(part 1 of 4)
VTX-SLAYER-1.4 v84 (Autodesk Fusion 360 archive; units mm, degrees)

design "VTX-SLAYER-1.0" references "prop", "M2 screw size FLAT WASHER", "motor", "M3 x 0.5mm Thread 16mm LONG SOCKET HEAD CAP SCREW", "M2 x 0.4mm Thread 5mm LONG SOCKET HEAD CAP SCREW", "M2 x 0.4mm Thread 6mm LONG SOCKET HEAD CAP SCREW", "M2 x 0.4mm Thread HEX NUT", "runcam_phoenix_2", "M2 x 0.4mm Thread 20mm LONG SOCKET HEAD CAP SCREW", "nut", "M3 x 0.5mm Thread 8mm LONG SOCKET HEAD CAP SCREW", "vtx-slayer-caddx-antenna-mount"
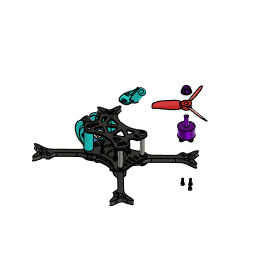
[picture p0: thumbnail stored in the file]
parameter "d278" = 4.1
parameter "d427" = 3.1
parameter "d437" = 4.2
parameter "d451" = 2.2
parameter "d614" = 15
parameter "d1109" = 4
parameter "d1134" = 12.8 (= "25.6 mm / 2.0")
canvas "Ansichtsbereich"
sketch "Skizze1" plane through (0, 0, 0) normal (0, 0, 1) x axis (1, 0, 0)
  line L1 (5.8693, -34.9991) -> (5.8693, -25.0204)
  line L2 (-57.0019, 8.0109) -> (-57.5891, 7.9385)
  line L3 (-57.259, 10.0951) -> (-57.8463, 10.0227)
  line L4 (-53.0046, 14.7338) -> (-53.0363, 15.3314)
  line L5 (-50.9075, 14.8451) -> (-50.9392, 15.4427)
  line L6 (-45.7643, 10.7703) -> (-46.3634, 10.7515)
  line L7 (-46.2975, 8.6525) -> (-45.6984, 8.6714)
  line L8 (0.8693, -39.9991) -> (-14.9589, -39.9991)
  line L9 (5.2623, -39.9991) -> (0.8693, -39.9991)
  line L10 (5.8693, -39.9991) -> (5.2623, -39.9991)
  line L11 (5.8693, -34.9991) -> (5.8693, -39.9991)
  line L12 (15.8693, -49.9991) -> (15.873, -49.9991)
  line L13 (15.8693, -29.9991) -> (15.873, -29.9991)
  line L14 (-7.6307, -25.3947) -> (-7.6307, -34.4991)
  curve K1 (-7.6307, -25.3947) -> (-10.9746, -20.0338)
  curve K2 (-12.5574, -19.204) -> (-9.3918, -20.8636)
  curve K3 (-7.6307, -25.7698) -> (-7.6307, -25.0196)
  line L15 (-20.2292, -25.643) -> (-53.829, 7.2456)
  line L16 (-49.632, 11.5333) -> (-16.0322, -21.3552)
  curve K4 (-25.1132, -12.4665) -> (-14.076, -18.1856)
  curve K5 (-42.6895, -3.6581) -> (-58.4159, 4.3179)
  curve K6 (-39.5769, 1.6911) -> (-43.0511, 12.8356)
  curve K7 (-39.0355, 1.1612) -> (-40.1182, 2.221)
  curve K8 (-42.3474, 12.2194) -> (-43.7548, 13.4517)
  curve K9 (-41.833, -4.4965) -> (-43.5461, -2.8197)
  curve K10 (-57.742, 4.1664) -> (-59.0898, 4.4693)
  curve K11 (-26.2747, -11.3295) -> (-23.9517, -13.6034)
  curve K12 (-14.6037, -17.8994) -> (-13.5483, -18.4717)
  curve K13 (-26.9801, -19.0351) -> (-22.3176, -27.7327)
  curve K14 (-22.9195, -27.2509) -> (-21.7157, -28.2145)
  curve K15 (-27.6566, -18.3729) -> (-26.3035, -19.6973)
  line L17 (-65.0703, 8.0734) -> (-57.1305, 9.053)
  line L18 (-52.3801, 22.7782) -> (-51.956, 14.7895)
  curve K16 (5.8693, -25.0204) -> (-14.076, -18.1856)
  curve K17 (-12.5184, -19.0318) -> (-15.6337, -17.3393)
  curve K18 (10.1662, -25.0241) -> (1.5724, -25.0168)
  curve K19 (-22.3176, -27.7327) -> (-10.6307, -34.4991)
  curve K20 (-10.6307, -32.2321) -> (-10.6307, -36.7662)
  curve K21 (-17.5546, -29.5) -> (-14.0454, -29.5)
  curve K22 (-23.5931, -26.7897) -> (-21.042, -28.6757)
  curve K23 (-43.0511, 12.8356) -> (-47.6742, 16.5575)
  curve K24 (-47, 15.6) -> (-48.3483, 17.515)
  curve K25 (-42.3474, 12.2194) -> (-43.7548, 13.4517)
  curve K26 (-47.6742, 16.5575) -> (-58.4159, 4.3179)
  curve K27 (-62.844, 5.395) -> (-53.9878, 3.2408)
  curve K28 (-65.2846, 9.8103) -> (-64.856, 6.3366)
  curve K29 (-54.7508, 15.3088) -> (-57.8176, 12.0705)
  curve K30 (-50.6326, 22.871) -> (-54.1277, 22.6854)
  curve K31 (-46.4995, 14.804) -> (-48.8488, 18.311)
  circle C1 centre (-51.7305, 9.3895) radius 2.7
  circle C2 centre (-57.7177, 8.9806) radius 1.05
  circle C3 centre (-57.1305, 9.053) radius 1.05
  circle C4 centre (-51.9878, 15.3871) radius 1.05
  circle C5 centre (-51.956, 14.7895) radius 1.05
  circle C6 centre (-46.3305, 9.702) radius 1.05
  circle C7 centre (-45.7313, 9.7208) radius 1.05
  circle C8 centre (-18.1307, -23.4991) radius 1.55
  circle C9 centre (-4.1307, -29.9991) radius 1.05
  circle C10 centre (15.873, -29.9991) radius 1.05
  circle C11 centre (29.8693, -23.4991) radius 1.55
  circle C12 centre (5.8693, -39.9991) radius 5
  circle C13 centre (-18.1307, -56.4991) radius 1.55
  circle C14 centre (15.873, -49.9991) radius 1.05
  circle C15 centre (29.8693, -56.4991) radius 1.55
  circle C16 centre (-4.1307, -49.9991) radius 1.05
  circle C17 centre (-9.1307, -34.4991) radius 1.5
  circle C18 centre (-18.1307, -23.4991) radius 3
  circle C19 centre (-51.7305, 9.3895) radius 3
  point P12 (-57.0019, 8.0109)
  point P11 (-57.5891, 7.9385)
  point P14 (-57.259, 10.0951)
  point P13 (-57.8463, 10.0227)
  point P15 (-53.0363, 15.3314)
  point P18 (-50.9075, 14.8451)
  point P19 (-46.3634, 10.7515)
  point P20 (-45.7643, 10.7703)
  point P21 (-45.6984, 8.6714)
  point P22 (-46.2975, 8.6525)
  point P17 (-50.9392, 15.4427)
  point P16 (-53.0046, 14.7338)
  point P29 (0.8693, -39.9991)
  point P30 (5.8693, -34.9991)
  point P24 (-18.1307, -23.4991)
  point P27 (29.8693, -23.4991)
  point P28 (5.8693, -39.9991)
  point P32 (5.8693, -39.9991)
  point P34 (15.873, -49.9991)
  point P36 (15.873, -49.9991)
  point P26 (15.873, -29.9991)
  point P38 (15.873, -29.9991)
  point P41 (-10.6307, -34.4991)
  point P43 (-9.1307, -34.4991)
  point P44 (-7.6307, -34.4991)
  point P46 (-10.9746, -20.0338)
  point P45 (-7.6307, -25.3947)
  point P49 (-7.6307, -25.7698)
  point P52 (-53.829, 7.2456)
  point P53 (-20.2292, -25.643)
  point P54 (-16.0322, -21.3552)
  point P55 (-49.632, 11.5333)
  point P23 (-14.076, -18.1856)
  point P56 (-14.076, -18.1856)
  point P57 (-25.1132, -12.4665)
  point P58 (-42.6895, -3.6581)
  point P59 (-39.5769, 1.6911)
  point P61 (-39.0355, 1.1612)
  point P86 (-43.0511, 12.8356)
  point P65 (-41.833, -4.4965)
  point P85 (-58.4159, 4.3179)
  point P69 (-26.2747, -11.3295)
  point P73 (-26.9801, -19.0351)
  point P72 (-22.3176, -27.7327)
  point P77 (-27.6566, -18.3729)
  point P6 (-57.1305, 9.053)
  point P81 (-57.1305, 9.053)
  point P8 (-51.956, 14.7895)
  point P83 (-51.956, 14.7895)
  point P7 (-51.9878, 15.3871)
  point P5 (-57.7177, 8.9806)
  point P78 (-65.0703, 8.0734)
  point P82 (-65.0703, 8.0734)
  point P80 (-52.3801, 22.7782)
  point P84 (-52.3801, 22.7782)
  point P4 (5.8693, -25.0204)
  point P42 (-15.8, -29.5)
  point P97 (-47.6742, 16.5575)
  point P79 (-56.2842, 13.6897)
  point P112 (-10.9746, -20.0338)
  point P70 (-13.5483, -18.4717)
  point P62 (-43.7548, 13.4517)
  point P100 (-43.7548, 13.4517)
  point P25 (-4.1307, -29.9991)
  point P39 (15.8693, -29.9991)
  point P2 (-51.7305, 9.3895)
  point P9 (-46.3305, 9.702)
  point P37 (15.8693, -49.9991)
  point P40 (-4.1307, -49.9991)
  point P3 (-14.9589, -39.9991)
  point P104 (-64.856, 6.3366)
  point P105 (-65.2846, 9.8103)
  point P108 (-54.1277, 22.6854)
  point P109 (-50.6326, 22.871)
  horizontal L8
  perpendicular L1 L8
  coincident C3 P12
  tangent C3 L2
  coincident C2 P11
  tangent C2 L2
  coincident C3 P14
  tangent C3 L3
  coincident C2 P13
  tangent C2 L3
  coincident C4 P15
  tangent C4 L4
  tangent C5 L4
  coincident C5 P18
  tangent C5 L5
  tangent C4 L5
  coincident C6 P19
  tangent C6 L6
  coincident C7 P20
  tangent C7 L6
  coincident C7 P21
  tangent C7 L7
  coincident C6 P22
  tangent C6 L7
  coincident C4 P17
  coincident C5 P16
  coincident C12 P29
  coincident C12 P30
  perpendicular L1 L9
  horizontal P24 P27
  parallel L9 L10
  perpendicular L9 L11
  coincident P28 P32
  symmetric C8 L8 C13
  symmetric C10 L8 C14
  symmetric C11 L8 C15
  coincident P34 P36
  coincident P26 P38
  parallel L12 L13
  symmetric C9 L8 C16
  coincident P41 C17
  horizontal P41 P43
  coincident C17 P44
  tangent C17 L14
  vertical L14
  midpoint P46 K2
  midpoint P45 K3
  coincident L14 P49
  concentric C8 C18
  concentric C1 C19
  coincident C19 P52
  coincident C18 P53
  tangent C18 L15
  coincident C18 P54
  coincident C19 P55
  tangent C19 L16
  tangent C19 L15
  tangent C18 L16
  coincident P23 P56
  coincident L16 P57
  coincident L15 P58
  coincident L16 P59
  midpoint P59 K7
  coincident L16 P61
  parallel L16 K7
  midpoint K8 P86
  midpoint P58 K9
  coincident L15 P65
  parallel L15 K9
  midpoint K10 P85
  midpoint P57 K11
  coincident L16 P69
  midpoint P56 K12
  coincident L15 P73
  midpoint P72 K14
  midpoint P73 K15
  coincident L15 P77
  parallel L15 K15
  coincident P6 P81
  coincident P8 P83
  coincident P7 L18
  coincident P5 L17
  coincident P78 P82
  coincident P80 P84
  midpoint P23 K17
  midpoint P4 K18
  midpoint P41 K20
  midpoint P42 K21
  midpoint P72 K22
  midpoint P97 K24
  midpoint P86 K25
  midpoint P85 K27
  midpoint P78 K28
  midpoint P79 K29
  midpoint P80 K30
  midpoint P97 K31
  coincident P46 P112
  coincident P70 K16
  perpendicular L17 K28
  perpendicular L18 K30
  coincident P62 P100
  dimension "d4" diameter C1 = 5.4
  dimension "d8" diameter C2 = 2.1
  dimension "d9" diameter C3 = 2.1
  dimension "d10" diameter C4 = 2.1
  dimension "d11" diameter C5 = 2.1
  dimension "d12" diameter C6 = 2.1
  dimension "d13" diameter C7 = 2.1
  dimension "d14" diameter C8 = 3.1
  dimension "d16" diameter C9 = 2.1
  dimension "d17" diameter C10 = 2.1 (= "d16")
  dimension "d20" diameter C11 = 3.1 (= "d14")
  dimension "d23" distance P25 P39 = 20
  dimension "d27" diameter C12 = 10
  dimension "d50" distance P4 P28 = 14.9787
  dimension "d58" distance P24 P27 = 48 (= "d103 * 2")
  dimension "d102" distance L1 P25 = 10
  dimension "d103" distance L1 P24 = 24
  dimension "d145" distance P2 P6 = 5.4
  dimension "d146" distance P2 P9 = 5.4
  dimension "d148" distance P2 P8 = 5.4
  dimension "d265" distance P2 L1 = 57.5997
  dimension "d266" distance P2 L8 = 49.3886
  dimension "d267" distance P24 L8 = 16.5
  dimension "d272" distance P25 L8 = 10
  dimension "d273" distance P37 P39 = 20
  dimension "d274" distance P37 P40 = 20
  dimension "d520" diameter C17 = 3
  dimension "d521" distance P28 P43 = 15
  dimension "d522" distance L8 P43 = 5.5
  dimension "d523" distance P3 P29 = 15.8282
  dimension "d669" diameter C18 = 6
  dimension "d670" diameter C19 = 6
  dimension "d709" distance P83 P84 = 8
  dimension "d710" distance P81 P82 = 8
  dimension "d1085" distance P104 P105 = 3.5
  dimension "d1086" distance P108 P109 = 3.5
extrude "Extrusion4" new body sketch "Skizze1" profile of C1 K23 C2 C3 C4 C5 C6 C7 L2 L3 L4 L5 L6 L7 C8 K19 C17 L14 K1 L15 L16 K4 K5 K6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 along normal blind 5 bodies "arm-fr"
work_plane "Arbeitsebene3" RotateAngle -90
work_plane "Arbeitsebene4" RotateAngle 90
mirror "Spiegeln6" mirrorStitchTolerance 0.1 bodies "arm-rr"
mirror "Spiegeln7" mirrorStitchTolerance 0.1 bodies "arm-fl", "arm-rl"
sketch "Skizze43" plane through (0, 0, 5) normal (0, 0, 1) x axis (-1, 0, 0)
  line L1 (53.0363, -15.3314) -> (53.0046, -14.7338)
  line L2 (50.9075, -14.8451) -> (50.9392, -15.4427)
  line L3 (45.7643, -10.7703) -> (46.3634, -10.7515)
  line L4 (46.2975, -8.6525) -> (45.6984, -8.6714)
  line L5 (57.5891, -7.9385) -> (57.0019, -8.0109)
  line L6 (57.259, -10.0951) -> (57.8463, -10.0227)
  curve K1 (10.6307, 34.4991) -> (22.3176, 27.7327)
  line L7 (53.0046, 94.732) -> (53.0363, 95.3296)
  line L8 (50.9392, 95.441) -> (50.9075, 94.8433)
  line L9 (45.6984, 88.6696) -> (46.2975, 88.6508)
  line L10 (46.3634, 90.7497) -> (45.7643, 90.7686)
  line L11 (57.0019, 88.0092) -> (57.5891, 87.9367)
  line L12 (57.8463, 90.0209) -> (57.259, 90.0934)
  curve K2 (10.6307, 45.4991) -> (22.3176, 52.2655)
  line L13 (-64.7748, 95.3296) -> (-64.7431, 94.732)
  line L14 (-62.646, 94.8433) -> (-62.6778, 95.441)
  line L15 (-57.5028, 90.7686) -> (-58.1019, 90.7497)
  line L16 (-58.0361, 88.6508) -> (-57.4369, 88.6696)
  line L17 (-69.3276, 87.9367) -> (-68.7404, 88.0092)
  line L18 (-68.9976, 90.0934) -> (-69.5848, 90.0209)
  curve K3 (-22.3693, 45.4991) -> (-34.0561, 52.2655)
  line L19 (-64.7431, -14.7338) -> (-64.7748, -15.3314)
  line L20 (-62.6778, -15.4427) -> (-62.646, -14.8451)
  line L21 (-57.4369, -8.6714) -> (-58.0361, -8.6525)
  line L22 (-58.1019, -10.7515) -> (-57.5028, -10.7703)
  line L23 (-68.7404, -8.0109) -> (-69.3276, -7.9385)
  line L24 (-69.5848, -10.0227) -> (-68.9976, -10.0951)
  curve K4 (-22.3693, 34.4991) -> (-34.0561, 27.7327)
  line L25 (-2.454, 39.9991) -> (16.5436, 39.9991)
  line L26 (-5.8693, 35.997) -> (-5.8693, 24.0226)
  line L27 (-45, 39.9991) -> (35, 39.9991)
  line L28 (-5.8693, 61) -> (-5.8693, 13.9501)
  curve K5 (14.9589, 39.9991) -> (13.0937, 29.8846)
  curve K6 (5.0594, 23.381) -> (7.6307, 25.3947)
  curve K7 (7.6307, 23.731) -> (7.6307, 27.0584)
  curve K8 (3.3466, 23.9517) -> (6.7722, 22.8102)
  curve K9 (14.9589, 42.2662) -> (14.9589, 37.732)
  curve K10 (14.715, 29.209) -> (11.4725, 30.5602)
  curve K11 (15.7694, 31.8891) -> (15.1694, 30.2891)
  line L29 (-5.8693, 33.7991) -> (3.3307, 33.7991)
  line L30 (7.6307, 25.3947) -> (7.6307, 34.4991)
  curve K12 (9.6778, 20.9358) -> (7.6307, 25.3947)
  line L31 (-19.3693, 54.6035) -> (-19.3693, 45.4991)
  curve K13 (-21.4163, 59.0625) -> (-19.3693, 54.6035)
  line L32 (-19.3693, 34.4991) -> (-19.3693, 25.3947)
  line L33 (7.6307, 45.4991) -> (7.6307, 54.6035)
  curve K14 (10.9746, 20.0338) -> (9.6778, 20.9358)
  curve K15 (-22.7131, 59.9644) -> (-21.4163, 59.0625)
  curve K16 (9.6778, 59.0625) -> (7.6307, 54.6035)
  curve K17 (-21.4163, 20.9358) -> (-19.3693, 25.3947)
  curve K18 (10.9746, 59.9644) -> (9.6778, 59.0625)
  curve K19 (-22.7131, 20.0338) -> (-21.4163, 20.9358)
  curve K20 (43.0511, -12.8356) -> (39.5769, -1.6911)
  curve K21 (25.1132, 12.4665) -> (14.076, 18.1856)
  line L34 (39.5769, -1.6911) -> (25.1132, 12.4665)
  curve K22 (43.0511, 92.8338) -> (39.5769, 81.6893)
  line L35 (25.1132, 67.5318) -> (39.5769, 81.6893)
  curve K23 (25.1132, 67.5318) -> (14.076, 61.8127)
  curve K24 (47.6742, 96.5557) -> (43.0511, 92.8338)
  curve K25 (-54.7896, 92.8338) -> (-51.3154, 81.6893)
  curve K26 (-36.8517, 67.5318) -> (-25.8145, 61.8127)
  line L36 (-51.3154, 81.6893) -> (-36.8517, 67.5318)
  curve K27 (-54.7896, -12.8356) -> (-51.3154, -1.6911)
  line L37 (-36.8517, 12.4665) -> (-51.3154, -1.6911)
  curve K28 (-36.8517, 12.4665) -> (-25.8145, 18.1856)
  curve K29 (-59.4127, -16.5575) -> (-54.7896, -12.8356)
  curve K30 (42.6895, 3.6581) -> (58.4159, -4.3179)
  line L38 (26.9801, 19.0351) -> (42.6895, 3.6581)
  curve K31 (22.3176, 27.7327) -> (26.9801, 19.0351)
  curve K32 (22.3176, 52.2655) -> (26.9801, 60.9632)
  line L39 (42.6895, 76.3401) -> (26.9801, 60.9632)
  curve K33 (42.6895, 76.3401) -> (58.4159, 84.3161)
  curve K34 (-59.4127, 96.5557) -> (-54.7896, 92.8338)
  curve K35 (-54.4281, 76.3401) -> (-70.1544, 84.3161)
  line L40 (-38.7186, 60.9632) -> (-54.4281, 76.3401)
  curve K36 (-34.0561, 52.2655) -> (-38.7186, 60.9632)
  curve K37 (-34.0561, 27.7327) -> (-38.7186, 19.0351)
  line L41 (-54.4281, 3.6581) -> (-38.7186, 19.0351)
  curve K38 (-54.4281, 3.6581) -> (-70.1544, -4.3179)
  curve K39 (52.3801, -22.7782) -> (47.6742, -16.5575)
  curve K40 (65.0703, -8.0734) -> (52.3801, -22.7782)
  curve K41 (52.3801, 102.7764) -> (47.6742, 96.5557)
  curve K42 (-64.1186, 102.7764) -> (-59.4127, 96.5557)
  curve K43 (-76.8088, 88.0717) -> (-64.1186, 102.7764)
  curve K44 (-64.1186, -22.7782) -> (-59.4127, -16.5575)
  curve K45 (65.0703, 88.0717) -> (52.3801, 102.7764)
  curve K46 (-76.8088, -8.0734) -> (-64.1186, -22.7782)
  curve K47 (-5.8693, 25.0204) -> (14.076, 18.1856)
  curve K48 (58.4159, -4.3179) -> (65.0703, -8.0734)
  curve K49 (58.4159, 84.3161) -> (65.0703, 88.0717)
  curve K50 (-70.1544, 84.3161) -> (-76.8088, 88.0717)
  curve K51 (-70.1544, -4.3179) -> (-76.8088, -8.0734)
  curve K52 (14.076, 18.1856) -> (10.9746, 20.0338)
  curve K53 (47.6742, -16.5575) -> (43.0511, -12.8356)
  curve K54 (14.076, 61.8127) -> (10.9746, 59.9644)
  curve K55 (-25.8145, 18.1856) -> (-22.7131, 20.0338)
  curve K56 (-25.8145, 61.8127) -> (-22.7131, 59.9644)
  arc A1 centre (51.9878, -15.3871) radius 1.05 clockwise from (53.0363, -15.3314) to (50.9392, -15.4427)
  arc A2 centre (51.956, -14.7895) radius 1.05 clockwise from (50.9075, -14.8451) to (53.0046, -14.7338)
  circle C1 centre (18.1307, 23.4991) radius 1.55
  arc A3 centre (46.3305, -9.702) radius 1.05 clockwise from (46.2975, -8.6525) to (46.3634, -10.7515)
  arc A4 centre (45.7313, -9.7208) radius 1.05 clockwise from (45.7643, -10.7703) to (45.6984, -8.6714)
  arc A5 centre (57.7177, -8.9806) radius 1.05 clockwise from (57.5891, -7.9385) to (57.8463, -10.0227)
  arc A6 centre (57.1305, -9.053) radius 1.05 clockwise from (57.259, -10.0951) to (57.0019, -8.0109)
  circle C2 centre (51.7305, -9.3895) radius 2.7
  arc A7 centre (9.1307, 34.4991) radius 1.5 clockwise from (7.6307, 34.4991) to (10.6307, 34.4991)
  arc A8 centre (51.956, 94.7877) radius 1.05 clockwise from (53.0046, 94.732) to (50.9075, 94.8433)
  arc A9 centre (51.9878, 95.3853) radius 1.05 clockwise from (50.9392, 95.441) to (53.0363, 95.3296)
  circle C3 centre (18.1307, 56.4991) radius 1.55
  arc A10 centre (46.3305, 89.7003) radius 1.05 clockwise from (46.3634, 90.7497) to (46.2975, 88.6508)
  arc A11 centre (45.7313, 89.7191) radius 1.05 clockwise from (45.6984, 88.6696) to (45.7643, 90.7686)
  arc A12 centre (57.1305, 89.0513) radius 1.05 clockwise from (57.0019, 88.0092) to (57.259, 90.0934)
  arc A13 centre (57.7177, 88.9788) radius 1.05 clockwise from (57.8463, 90.0209) to (57.5891, 87.9367)
  circle C4 centre (51.7305, 89.3877) radius 2.7
  arc A14 centre (9.1307, 45.4991) radius 1.5 clockwise from (10.6307, 45.4991) to (7.6307, 45.4991)
  arc A15 centre (-63.7263, 95.3853) radius 1.05 clockwise from (-64.7748, 95.3296) to (-62.6778, 95.441)
  arc A16 centre (-63.6946, 94.7877) radius 1.05 clockwise from (-62.646, 94.8433) to (-64.7431, 94.732)
  circle C5 centre (-29.8693, 56.4991) radius 1.55
  arc A17 centre (-58.069, 89.7003) radius 1.05 clockwise from (-58.0361, 88.6508) to (-58.1019, 90.7497)
  arc A18 centre (-57.4698, 89.7191) radius 1.05 clockwise from (-57.5028, 90.7686) to (-57.4369, 88.6696)
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  point P107 (13.0937, 29.8846)
  point P111 (-5.8693, 39.9991)
  point P109 (7.6307, 25.3947)
  point P110 (5.0594, 23.381)
  point P108 (15.4694, 31.0891)
  point P128 (-5.8693, 33.7991)
  point P114 (7.6307, 27.0584)
  parallel L25 L27
  perpendicular L27 L28
  coincident K1 P107
  coincident L28 P111
  coincident L27 P111
  midpoint P109 K7
  midpoint P110 K8
  midpoint P107 K10
  midpoint P108 K11
  horizontal L29
  coincident L26 P128
  coincident L28 P128
  parallel L28 K9
  coincident P109 L30
  coincident P114 L30
  dimension "d356" diameter = 4.2
  dimension "d363" diameter = 3.1
  dimension "d503" distance P111 P128 = 6.2
extrude "Extrusion55" new body sketch "Skizze43" against normal blind 2 bodies "m-center"
mirror "Spiegeln20" mirrorStitchTolerance 0.1
mirror "Spiegeln21" mirrorStitchTolerance 0.1
sketch "Skizze4" plane through (0, 0, 0) normal (0, 0, -1) x axis (1, 0, 0)
  line L1 (-45.6984, -8.6714) -> (-46.2975, -8.6525)
  line L2 (-46.3634, -10.7515) -> (-45.7643, -10.7703)
  line L3 (-53.0046, -14.7338) -> (-53.0363, -15.3314)
  line L4 (-50.9392, -15.4427) -> (-50.9075, -14.8451)
  line L5 (-57.0019, -8.0109) -> (-57.5891, -7.9385)
  line L6 (-57.8463, -10.0227) -> (-57.259, -10.0951)
  line L7 (5.8693, 34.9991) -> (5.8693, 39.9991)
  line L8 (5.8693, 34.9991) -> (5.8693, 25.0204)
  curve K1 (-22.3176, 27.7327) -> (-10.6307, 34.4991)
  curve K2 (-13.2943, 29.8104) -> (-14.9589, 39.9991)
  curve K3 (-13.0937, 29.8846) -> (-13.2943, 29.8104)
  curve K4 (-5.4893, 23.275) -> (-7.6307, 25.3947)
  line L9 (-34.1307, 39.9991) -> (5.8693, 39.9991)
  line L10 (-34.1307, 46.2008) -> (-34.1307, 39.9991)
  line L11 (-12.5862, 69.6661) -> (-34.1307, 46.2008)
  line L12 (-57.5891, 87.9367) -> (-57.0019, 88.0092)
  line L13 (-57.259, 90.0934) -> (-57.8463, 90.0209)
  line L14 (-53.0363, 95.3296) -> (-53.0046, 94.732)
  line L15 (-50.9075, 94.8433) -> (-50.9392, 95.441)
  line L16 (-45.7643, 90.7686) -> (-46.3634, 90.7497)
  line L17 (-46.2975, 88.6508) -> (-45.6984, 88.6696)
  curve K5 (-22.3176, 52.2655) -> (-10.6307, 45.4991)
  curve K6 (-1.6863, 55.6114) -> (-9.6778, 59.0625)
  curve K7 (0.3253, 55.2725) -> (-3.698, 55.9502)
  curve K8 (-3.0083, 56.2858) -> (-3.1917, 58.5142)
  curve K9 (-8.5538, 58.2617) -> (-10.8018, 59.8633)
  curve K10 (-2.18, 58.2549) -> (-5.9502, 58.4922)
  line L18 (5.8693, 35.997) -> (5.8693, 24.0226)
  line L19 (68.7404, 88.0092) -> (69.3276, 87.9367)
  line L20 (69.5848, 90.0209) -> (68.9976, 90.0934)
  line L21 (64.7431, 94.732) -> (64.7748, 95.3296)
  line L22 (62.6778, 95.441) -> (62.646, 94.8433)
  line L23 (57.4369, 88.6696) -> (58.0361, 88.6508)
  line L24 (58.1019, 90.7497) -> (57.5028, 90.7686)
  curve K11 (34.0561, 52.2655) -> (22.3693, 45.4991)
  curve K12 (26.6564, 39.9983) -> (33.3763, 51.7943)
  curve K13 (26.6564, 38.371) -> (26.6564, 41.6256)
  curve K14 (32.9215, 51.5105) -> (33.8311, 52.0782)
  line L25 (40, 39.9991) -> (5.8693, 39.9991)
  line L26 (-29.6307, 42.9991) -> (-13.1687, 42.9991)
  line L27 (-13.1687, 48.9991) -> (-25.1307, 48.9991)
  line L28 (-13.1687, 42.9991) -> (-13.1687, 48.9991)
  line L29 (-20.1687, 42.9991) -> (-29.6307, 42.9991)
  line L30 (-14.6007, 50.4991) -> (-25.1307, 50.4991)
  line L31 (-12.0137, 44.4991) -> (-29.6307, 44.4991)
  line L32 (-12.0137, 41.4991) -> (-29.6307, 41.4991)
  line L33 (-14.6007, 47.4991) -> (-25.1307, 47.4991)
  curve K15 (-7.6307, 25.3947) -> (-9.6778, 20.9358)
  line L34 (-7.6307, 34.4991) -> (-7.6307, 25.3947)
  line L35 (-7.6307, 25.3947) -> (-7.6307, 34.4991)
  line L36 (-7.6307, 54.6035) -> (-7.6307, 45.4991)
  curve K16 (19.3693, 54.6035) -> (21.4163, 59.0625)
  line L37 (19.3693, 45.4991) -> (19.3693, 54.6035)
  line L38 (24.3247, 69.6661) -> (45.8693, 46.2008)
  curve K17 (-7.6307, 54.6035) -> (-9.6778, 59.0625)
  curve K18 (13.4249, 55.6114) -> (21.4163, 59.0625)
  curve K19 (20.2923, 58.2617) -> (22.5404, 59.8633)
  curve K20 (13.9185, 58.2549) -> (17.6888, 58.4922)
  curve K21 (14.7469, 56.2858) -> (14.9302, 58.5142)
  curve K22 (11.4132, 55.2725) -> (15.4365, 55.9502)
  line L39 (22.3617, 39.9991) -> (22.3693, 45.4966)
  curve K23 (-9.6778, 20.9358) -> (-10.9746, 20.0338)
  curve K24 (21.4163, 59.0625) -> (22.7131, 59.9644)
  curve K25 (-39.5769, -1.6911) -> (-43.0511, -12.8356)
  line L40 (-25.1132, 12.4665) -> (-39.5769, -1.6911)
  curve K26 (-25.1132, 12.4665) -> (-14.076, 18.1856)
  curve K27 (-39.5769, 81.6893) -> (-43.0511, 92.8338)
  curve K28 (-9.6778, 59.0625) -> (-10.9746, 59.9644)
  curve K29 (-25.1132, 67.5318) -> (-14.076, 61.8127)
  line L41 (-39.5769, 81.6893) -> (-25.1132, 67.5318)
  curve K30 (51.3154, 81.6893) -> (54.7896, 92.8338)
  line L42 (36.8517, 67.5318) -> (51.3154, 81.6893)
  curve K31 (36.8517, 67.5318) -> (25.8145, 61.8127)
  curve K32 (-26.9801, 19.0351) -> (-22.3176, 27.7327)
  line L43 (-42.6895, 3.6581) -> (-26.9801, 19.0351)
  curve K33 (-42.6895, 3.6581) -> (-58.4159, -4.3179)
  curve K34 (-42.6895, 76.3401) -> (-58.4159, 84.3161)
  line L44 (-26.9801, 60.9632) -> (-42.6895, 76.3401)
  curve K35 (-26.9801, 60.9632) -> (-22.3176, 52.2655)
  curve K36 (38.7186, 60.9632) -> (34.0561, 52.2655)
  line L45 (54.4281, 76.3401) -> (38.7186, 60.9632)
  curve K37 (54.4281, 76.3401) -> (70.1544, 84.3161)
  line L46 (10.0693, 50.9491) -> (1.6693, 50.9491)
  line L47 (10.0693, 47.4491) -> (1.6693, 47.4491)
  curve K38 (-10.6307, 34.4991) -> (-13.0937, 29.8846)
  curve K39 (17.2278, 23.275) -> (19.3693, 25.3947)
  line L48 (19.3693, 34.4991) -> (19.3693, 25.3947)
  curve K40 (22.3693, 34.4991) -> (24.8323, 29.8846)
  curve K41 (24.8323, 29.8846) -> (25.0329, 29.8104)
  curve K42 (25.0329, 29.8104) -> (26.6974, 39.9991)
  curve K43 (25.0329, 50.1878) -> (26.6974, 39.9991)
  curve K44 (24.8323, 50.1137) -> (25.0329, 50.1878)
  curve K45 (22.3693, 45.4991) -> (24.8323, 50.1137)
  line L49 (19.3693, 54.6035) -> (19.3693, 45.4991)
  curve K46 (17.2278, 56.7233) -> (19.3693, 54.6035)
  curve K47 (-5.4893, 56.7233) -> (-7.6307, 54.6035)
  line L50 (-7.6307, 45.4991) -> (-7.6307, 54.6035)
  curve K48 (-10.6307, 45.4991) -> (-13.0937, 50.1137)
  curve K49 (-13.0937, 50.1137) -> (-13.2943, 50.1878)
  curve K50 (-13.2943, 50.1878) -> (-14.9589, 39.9991)
  curve K51 (-52.3801, -22.7782) -> (-65.0703, -8.0734)
  curve K52 (-47.6742, -16.5575) -> (-52.3801, -22.7782)
  curve K53 (-47.6742, 96.5557) -> (-52.3801, 102.7764)
  curve K54 (64.1186, 102.7764) -> (76.8088, 88.0717)
  curve K55 (59.4127, 96.5557) -> (64.1186, 102.7764)
  curve K56 (-43.0511, 92.8338) -> (-47.6742, 96.5557)
  curve K57 (-52.3801, 102.7764) -> (-65.0703, 88.0717)
  curve K58 (54.7896, 92.8338) -> (59.4127, 96.5557)
  curve K59 (5.8693, 54.9778) -> (17.2278, 56.7233)
  curve K60 (5.8693, 54.9778) -> (-5.4893, 56.7233)
  curve K61 (5.8693, 25.0204) -> (-5.4893, 23.275)
  curve K62 (5.8693, 25.0204) -> (17.2278, 23.275)
  curve K63 (-65.0703, -8.0734) -> (-58.4159, -4.3179)
  curve K64 (-65.0703, 88.0717) -> (-58.4159, 84.3161)
  curve K65 (76.8088, 88.0717) -> (70.1544, 84.3161)
  curve K66 (-10.9746, 20.0338) -> (-14.076, 18.1856)
  curve K67 (-10.9746, 59.9644) -> (-14.076, 61.8127)
  curve K68 (22.7131, 59.9644) -> (25.8145, 61.8127)
  arc A1 centre (-46.3305, -9.702) radius 1.05 clockwise from (-46.3634, -10.7515) to (-46.2975, -8.6525)
  arc A2 centre (-45.7313, -9.7208) radius 1.05 clockwise from (-45.6984, -8.6714) to (-45.7643, -10.7703)
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  point P73 (-1.6863, 55.6114)
  point P72 (-3.1, 57.4)
  point P70 (-9.6778, 59.0625)
  point P71 (-4.0651, 58.3735)
  point P110 (33.3763, 51.7943)
  point P22 (5.8693, 39.9991)
  point P115 (5.8693, 39.9991)
  point P118 (-29.6307, 42.9991)
  point P124 (-29.6307, 42.9991)
  point P125 (-12.0137, 42.9991)
  point P119 (-25.1307, 48.9991)
  point P126 (-25.1307, 48.9991)
  point P127 (-14.6007, 48.9991)
  point P136 (5.8693, 39.9991)
  point P41 (5.8693, 39.9991)
  point P44 (-34.1307, 46.2008)
  point P146 (45.8693, 46.2008)
  point P45 (-12.5862, 69.6661)
  point P147 (24.3247, 69.6661)
  point P152 (21.4163, 59.0625)
  point P153 (15.8036, 58.3735)
  point P154 (14.8385, 57.4)
  point P155 (13.4249, 55.6114)
  point P74 (-3.698, 55.9502)
  point P162 (15.4365, 55.9502)
  point P75 (0.3253, 55.2725)
  point P163 (11.4132, 55.2725)
  point P76 (-3.1917, 58.5142)
  point P160 (14.9302, 58.5142)
  point P77 (-3.0083, 56.2858)
  point P161 (14.7469, 56.2858)
  point P78 (-10.8018, 59.8633)
  point P156 (22.5404, 59.8633)
  point P79 (-8.5538, 58.2617)
  point P157 (20.2923, 58.2617)
  point P80 (-5.9502, 58.4922)
  point P158 (17.6888, 58.4922)
  point P81 (-2.18, 58.2549)
  point P159 (13.9185, 58.2549)
  point P165 (22.3617, 39.9991)
  point P117 (-13.1687, 42.9991)
  point P120 (-13.1687, 48.9991)
  point P43 (-34.1307, 39.9991)
  point P189 (1.6693, 49.1991)
  point P190 (10.0693, 49.1991)
  perpendicular L9 L10
  midpoint P73 K7
  midpoint P72 K8
  midpoint P70 K9
  midpoint P71 K10
  parallel L7 L10
  midpoint P110 K14
  coincident P22 P115
  perpendicular L7 L25
  horizontal L26
  horizontal L27
  vertical L28
  horizontal L29
  coincident P118 P124
  coincident L26 P125
  coincident P119 P126
  coincident L27 P127
  parallel L31 L32
  coincident P22 P136
  coincident P41 P136
  symmetric P44 L18 P146
  symmetric P45 L18 P147
  coincident P70 K17
  symmetric P70 L18 P152
  symmetric P71 L18 P153
  symmetric P72 L18 P154
  symmetric P73 L18 P155
  symmetric P74 L18 P162
  symmetric P75 L18 P163
  symmetric P76 L18 P160
  symmetric P77 L18 P161
  symmetric P78 L18 P156
  symmetric P79 L18 P157
  symmetric P80 L18 P158
  symmetric P81 L18 P159
  parallel L18 K13
  coincident L25 P165
  coincident K11 P110
  horizontal L46
  parallel L46 L47
  dimension "d397" distance P117 P120 = 6
  dimension "d399" distance L9 L26 = 3
  dimension "d472" diameter = 3
  dimension "d481" diameter = 3
  dimension "d482" diameter = 3
  dimension "d483" diameter = 3
  dimension "d510" diameter = 6
  dimension "d532" distance P41 P43 = 40
  dimension "d544" distance L10 P126 = 9
  dimension "d545" distance L10 P124 = 4.5
  dimension "d682" diameter = 3.5
  dimension "d683" diameter = 3.5
  dimension "d684" distance P115 P189 = 4.2
  dimension "d685" distance P115 P190 = 4.2
  dimension "d686" distance L9 P189 = 9.2
  dimension "d687" distance L25 P190 = 9.2
  dimension "d688" diameter = 4.2
extrude "Extrusion56" new body sketch "Skizze4" along normal blind 2 bodies "m-bottom"
fillet "Fillet26" radius 6
mirror "Spiegeln22" mirrorStitchTolerance 0.1
work_axis "Arbeitsachse" sketch "Skizze43"
fillet "Fillet32" radius 5
fillet "Fillet44" radius 5
copy_paste_bodies "CopyPasteBodies9"
move "Move19"
move "Move20" RotateAngle 180
sketch "topplate" plane through (0, 0, 7) normal (0, 0, 1) x axis (-1, 0, 0)
  curve K1 (9.811, 20.8371) -> (10.9746, 20.0338)
  line L1 (-26.3392, 50.4991) -> (-34.3693, 50.4991)
  line L2 (-34.3693, 47.4991) -> (-26.3392, 47.4991)
  line L3 (-23.7522, 44.4991) -> (-34.3693, 44.4991)
  line L4 (-34.3693, 41.4991) -> (-23.7522, 41.4991)
  line L5 (-2.8693, 49.9991) -> (-8.8693, 49.9991)
  line L6 (-8.8693, 45.9991) -> (-2.8693, 45.9991)
  line L7 (-2.8693, 33.9991) -> (-8.8693, 33.9991)
  line L8 (-8.8693, 29.9991) -> (-2.8693, 29.9991)
  line L9 (-23.7522, 38.4991) -> (-34.3693, 38.4991)
  line L10 (-34.3693, 35.4991) -> (-23.7522, 35.4991)
  line L11 (-26.3392, 32.4991) -> (-34.3693, 32.4991)
  line L12 (-34.3693, 29.4991) -> (-26.3392, 29.4991)
  curve K2 (14.9178, 39.9991) -> (14.9887, 41.536)
  curve K3 (14.9178, 39.9991) -> (14.9887, 38.4622)
  curve K4 (14.991, 38.4401) -> (21.2218, 28.4813)
  curve K5 (14.991, 41.5582) -> (21.2218, 51.5169)
  line L13 (21.0607, 60.4361) -> (21.7601, 59.6743)
  line L14 (-44.2889, 47.922) -> (-32.7992, 60.4361)
  line L15 (-45.8693, 36.1341) -> (-45.8693, 43.8641)
  line L16 (-32.7992, 19.5622) -> (-44.2889, 32.0762)
  line L17 (21.7601, 20.324) -> (21.0607, 19.5622)
  line L18 (-23.7522, 44.4991) -> (-41.3693, 44.4991)
  line L19 (-41.3693, 41.4991) -> (-23.7522, 41.4991)
  line L20 (-26.3392, 50.4991) -> (-36.8693, 50.4991)
  line L21 (-36.8693, 47.4991) -> (-26.3392, 47.4991)
  line L22 (-26.3392, 32.4991) -> (-36.8693, 32.4991)
  line L23 (-36.8693, 29.4991) -> (-26.3392, 29.4991)
  line L24 (-23.7522, 38.4991) -> (-41.3693, 38.4991)
  line L25 (-41.3693, 35.4991) -> (-23.7522, 35.4991)
  curve K6 (-21.4163, 59.0625) -> (-22.7131, 59.9644)
  curve K7 (-21.4163, 20.9358) -> (-22.7131, 20.0338)
  curve K8 (23.3399, 24.4614) -> (21.2218, 28.4813)
  curve K9 (21.2218, 51.5169) -> (23.3399, 55.5369)
  curve K10 (1.7709, 55.6283) -> (9.811, 59.1611)
  curve K11 (0.8783, 55.4553) -> (2.6635, 55.8012)
  curve K12 (9.0903, 58.6539) -> (10.5317, 59.6683)
  line L26 (-2.454, 39.9991) -> (16.5436, 39.9991)
  curve K13 (1.7709, 24.37) -> (9.811, 20.8371)
  curve K14 (9.0903, 21.3444) -> (10.5317, 20.3299)
  curve K15 (0.8783, 24.5429) -> (2.6635, 24.197)
  line L27 (-5.8693, 35.997) -> (-5.8693, 24.0226)
  curve K16 (-13.5094, 24.37) -> (-21.5495, 20.8371)
  curve K17 (-20.8288, 21.3444) -> (-22.2702, 20.3299)
  curve K18 (-12.6168, 24.5429) -> (-14.402, 24.197)
  curve K19 (-13.5094, 55.6283) -> (-21.5495, 59.1611)
  curve K20 (-20.8288, 58.6539) -> (-22.2702, 59.6683)
  curve K21 (-12.6168, 55.4553) -> (-14.402, 55.8012)
  curve K22 (-5.8693, 25.0204) -> (-13.4249, 24.3869)
  curve K23 (-5.8693, 25.0204) -> (1.6863, 24.3869)
  curve K24 (-5.8693, 54.9778) -> (1.6863, 55.6114)
  curve K25 (-5.8693, 54.9778) -> (-13.4249, 55.6114)
  curve K26 (14.9178, 39.9991) -> (14.991, 38.4401)
  curve K27 (14.9178, 39.9991) -> (14.991, 41.5582)
  curve K28 (13.7829, 61.6537) -> (21.0607, 60.4361)
  curve K29 (10.9746, 59.9644) -> (13.7829, 61.6537)
  curve K30 (-22.7131, 59.9644) -> (-25.5215, 61.6537)
  curve K31 (-32.7992, 60.4361) -> (-25.5215, 61.6537)
  curve K32 (-32.7992, 19.5622) -> (-25.5215, 18.3445)
  curve K33 (-22.7131, 20.0338) -> (-25.5215, 18.3445)
  curve K34 (10.9746, 20.0338) -> (13.7829, 18.3445)
  curve K35 (13.7829, 18.3445) -> (21.0607, 19.5622)
  curve K36 (9.6778, 59.0625) -> (10.9746, 59.9644)
  curve K37 (1.7709, 55.6283) -> (9.6778, 59.0625)
  curve K38 (1.6863, 55.6114) -> (1.7709, 55.6283)
  curve K39 (-13.4249, 55.6114) -> (-13.5094, 55.6283)
  curve K40 (-13.5094, 55.6283) -> (-21.4163, 59.0625)
  curve K41 (-13.5094, 24.37) -> (-21.4163, 20.9358)
  curve K42 (-13.4249, 24.3869) -> (-13.5094, 24.37)
  curve K43 (1.6863, 24.3869) -> (1.7709, 24.37)
  curve K44 (1.7709, 24.37) -> (9.6778, 20.9358)
  curve K45 (9.6778, 20.9358) -> (10.9746, 20.0338)
  arc A1 centre (-34.3693, 48.9991) radius 1.5 clockwise from (-34.3693, 47.4991) to (-34.3693, 50.4991)
  arc A2 centre (-26.3392, 48.9991) radius 1.5 clockwise from (-26.3392, 50.4991) to (-26.3392, 47.4991)
  arc A3 centre (-34.3693, 42.9991) radius 1.5 clockwise from (-34.3693, 41.4991) to (-34.3693, 44.4991)
  arc A4 centre (-23.7522, 42.9991) radius 1.5 clockwise from (-23.7522, 44.4991) to (-23.7522, 41.4991)
  circle C1 centre (-29.8693, 56.4991) radius 1.55
  arc A5 centre (-8.8693, 47.9991) radius 2 clockwise from (-8.8693, 45.9991) to (-8.8693, 49.9991)
  arc A6 centre (-2.8693, 47.9991) radius 2 clockwise from (-2.8693, 49.9991) to (-2.8693, 45.9991)
  arc A7 centre (-8.8693, 31.9991) radius 2 clockwise from (-8.8693, 29.9991) to (-8.8693, 33.9991)
  arc A8 centre (-2.8693, 31.9991) radius 2 clockwise from (-2.8693, 33.9991) to (-2.8693, 29.9991)
  circle C2 centre (-29.8693, 23.4991) radius 1.55
  arc A9 centre (-34.3693, 36.9991) radius 1.5 clockwise from (-34.3693, 35.4991) to (-34.3693, 38.4991)
  arc A10 centre (-23.7522, 36.9991) radius 1.5 clockwise from (-23.7522, 38.4991) to (-23.7522, 35.4991)
  arc A11 centre (-34.3693, 30.9991) radius 1.5 clockwise from (-34.3693, 29.4991) to (-34.3693, 32.4991)
  arc A12 centre (-26.3392, 30.9991) radius 1.5 clockwise from (-26.3392, 32.4991) to (-26.3392, 29.4991)
  circle C3 centre (-5.8693, 39.9991) radius 3
  circle C4 centre (18.1307, 23.4991) radius 2.55
  circle C5 centre (18.1307, 56.4991) radius 2.55
  circle C6 centre (-29.8693, 56.4991) radius 2.55
  circle C7 centre (-29.8693, 23.4991) radius 2.55
  circle C8 centre (4.1307, 29.9991) radius 1.05
  circle C9 centre (4.1307, 49.9991) radius 1.05
  circle C10 centre (-15.8693, 49.9991) radius 1.05
  circle C11 centre (-15.8693, 29.9991) radius 1.05
  circle C12 centre (-5.8693, 39.9991) radius 1.55
  circle C13 centre (-5.8693, 39.9991) radius 2.55
  arc A13 centre (-39.8693, 43.8641) radius 6 clockwise from (-45.8693, 43.8641) to (-44.2889, 47.922)
  arc A14 centre (-39.8693, 36.1341) radius 6 clockwise from (-44.2889, 32.0762) to (-45.8693, 36.1341)
  circle C14 centre (-5.8693, 39.9991) radius 3
  arc A15 centre (-41.3693, 42.9991) radius 1.5 clockwise from (-41.3693, 41.4991) to (-41.3693, 44.4991)
  arc A16 centre (-23.7522, 42.9991) radius 1.5 clockwise from (-23.7522, 44.4991) to (-23.7522, 41.4991)
  arc A17 centre (-36.8693, 48.9991) radius 1.5 clockwise from (-36.8693, 47.4991) to (-36.8693, 50.4991)
  arc A18 centre (-26.3392, 48.9991) radius 1.5 clockwise from (-26.3392, 50.4991) to (-26.3392, 47.4991)
  arc A19 centre (-36.8693, 30.9991) radius 1.5 clockwise from (-36.8693, 29.4991) to (-36.8693, 32.4991)
  arc A20 centre (-26.3392, 30.9991) radius 1.5 clockwise from (-26.3392, 32.4991) to (-26.3392, 29.4991)
  arc A21 centre (-41.3693, 36.9991) radius 1.5 clockwise from (-41.3693, 35.4991) to (-41.3693, 38.4991)
  arc A22 centre (-23.7522, 36.9991) radius 1.5 clockwise from (-23.7522, 38.4991) to (-23.7522, 35.4991)
  circle C15 centre (18.1307, 23.4991) radius 2.25
  circle C16 centre (-29.8693, 23.4991) radius 2.25
  circle C17 centre (18.1307, 56.4991) radius 2.25
  circle C18 centre (-29.8693, 56.4991) radius 2.25
  circle C19 centre (-5.8693, 39.9991) radius 2.25
  arc A23 centre (17.3404, 55.6164) radius 6 clockwise from (21.7601, 59.6743) to (23.3399, 55.5369)
  arc A24 centre (17.3404, 24.3819) radius 6 clockwise from (23.3399, 24.4614) to (21.7601, 20.324)
  circle C20 centre (-29.8693, 56.4991) radius 1.55
  circle C21 centre (-29.8693, 23.4991) radius 1.55
  arc A25 centre (4.1307, 29.9991) radius 2.1 clockwise from (4.1326, 32.0991) to (4.1326, 27.8991)
  arc A26 centre (4.1307, 49.9991) radius 2.1 clockwise from (4.1326, 52.0991) to (4.1326, 47.8991)
  arc A27 centre (4.1345, 29.9991) radius 2.1 clockwise from (4.1326, 27.8991) to (4.1326, 32.0991)
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  point P117 (1.7709, 55.6283)
  point P5 (9.811, 59.1611)
  point P124 (9.811, 20.8371)
  point P178 (1.7709, 24.37)
  point P118 (2.6635, 55.8012)
  point P127 (2.6635, 24.197)
  point P119 (0.8783, 55.4553)
  point P128 (0.8783, 24.5429)
  point P120 (10.5317, 59.6683)
  point P125 (10.5317, 20.3299)
  point P121 (9.0903, 58.6539)
  point P126 (9.0903, 21.3444)
  point P137 (-21.5495, 59.1611)
  point P138 (-13.5094, 55.6283)
  point P141 (-14.402, 55.8012)
  point P142 (-12.6168, 55.4553)
  point P139 (-22.2702, 59.6683)
  point P140 (-20.8288, 58.6539)
  point P131 (-21.5495, 20.8371)
  point P132 (-13.5094, 24.37)
  point P133 (-22.2702, 20.3299)
  point P134 (-20.8288, 21.3444)
  point P135 (-14.402, 24.197)
  point P136 (-12.6168, 24.5429)
  point P180 (1.7709, 24.37)
  concentric C1 C6
  concentric C2 C7
  concentric C3 C12
  concentric C12 C13
  concentric C4 C15
  concentric C2 C16
  concentric C1 C18
  concentric C13 C19
  midpoint P117 K11
  midpoint P5 K12
  symmetric P5 L26 P124
  symmetric P117 L26 P178
  symmetric P118 L26 P127
  symmetric P119 L26 P128
  symmetric P120 L26 P125
  symmetric P121 L26 P126
  symmetric P5 L27 P137
  symmetric P117 L27 P138
  symmetric P118 L27 P141
  symmetric P119 L27 P142
  symmetric P120 L27 P139
  symmetric P121 L27 P140
  symmetric P124 L27 P131
  symmetric L27 P132 P178
  symmetric P125 L27 P133
  symmetric P126 L27 P134
  symmetric P127 L27 P135
  symmetric P128 L27 P136
  coincident P178 P180
  dimension "d561" diameter C4 = 5.1
  dimension "d562" diameter C7 = 5.1 (= "d561")
  dimension "d563" diameter C6 = 5.1 (= "d561")
  dimension "d564" diameter C5 = 5.1 (= "d561")
  dimension "d565" diameter C8 = 2.1
  dimension "d566" diameter C11 = 2.1 (= "d565")
  dimension "d567" diameter C10 = 2.1 (= "d565")
  dimension "d568" diameter C9 = 2.1 (= "d565")
  dimension "d571" diameter C12 = 3.1
  dimension "d572" diameter C13 = 5.1 (= "d561")
  dimension "d641" diameter C15 = 4.5
  dimension "d642" diameter C16 = 4.5 (= "d641")
  dimension "d643" diameter C17 = 4.5 (= "d641")
  dimension "d644" diameter C18 = 4.5 (= "d641")
  dimension "d645" diameter C19 = 4.5 (= "d641")
extrude "Extrude73" add sketch "topplate" against normal blind 2
extrude "Extrude74" cut sketch "topplate" profile of C1 C2 C4 C5 C6 C7 C12 C13 C15 C16 C17 C18 C19 against normal blind 0.4
extrude "Extrude80" cut sketch "topplate" profile of C1 C2 C12 C15 C16 C17 C18 C19 against normal blind 1.1
extrude "Extrude81" cut sketch "topplate" profile of K10 L26 K13 K16 K19 against normal blind 2
sketch "top-chop" plane through (0, 0, 7) normal (0, 0, 1) x axis (-1, 0, 0)
  curve K1 (-34.0692, 39.9991) -> (-32.8495, 19.3496)
  curve K2 (-34.0384, 43.9982) -> (-34.1, 36)
  curve K3 (-34.2156, 20.7121) -> (-31.4834, 17.9871)
  line L1 (-2.454, 39.9991) -> (16.5436, 39.9991)
  curve K4 (-34.0692, 39.9991) -> (-32.8495, 60.6486)
  curve K5 (-34.2156, 59.2861) -> (-31.4834, 62.0111)
  curve K6 (-34.0384, 36) -> (-34.1, 43.9982)
  line L2 (-31.819, 50.4991) -> (-31.819, 29.4991)
  curve K7 (14.991, 38.4401) -> (21.2218, 28.4813)
  curve K8 (14.991, 41.5582) -> (21.2218, 51.5169)
  line L3 (21.0607, 60.4361) -> (21.7601, 59.6743)
  line L4 (-44.2889, 47.922) -> (-32.7992, 60.4361)
  line L5 (-45.8693, 36.1341) -> (-45.8693, 43.8641)
  line L6 (-32.7992, 19.5622) -> (-44.2889, 32.0762)
  line L7 (21.7601, 20.324) -> (21.0607, 19.5622)
  line L8 (-23.7522, 44.4991) -> (-41.3693, 44.4991)
  line L9 (-41.3693, 41.4991) -> (-23.7522, 41.4991)
  line L10 (-23.7522, 38.4991) -> (-41.3693, 38.4991)
  line L11 (-41.3693, 35.4991) -> (-23.7522, 35.4991)
  curve K9 (-21.4163, 59.0625) -> (-22.7131, 59.9644)
  curve K10 (-21.4163, 20.9358) -> (-22.7131, 20.0338)
  curve K11 (23.3399, 24.4614) -> (21.2218, 28.4813)
  curve K12 (21.2218, 51.5169) -> (23.3399, 55.5369)
  line L12 (-26.3392, 32.4991) -> (-34.3693, 32.4991)
  line L13 (-34.3693, 29.4991) -> (-26.3392, 29.4991)
  line L14 (-26.3392, 50.4991) -> (-34.3693, 50.4991)
  line L15 (-34.3693, 47.4991) -> (-26.3392, 47.4991)
  curve K13 (-5.8693, 25.0204) -> (1.6863, 24.3869)
  curve K14 (-5.8693, 54.9778) -> (1.6863, 55.6114)
  curve K15 (13.7829, 61.6537) -> (21.0607, 60.4361)
  curve K16 (10.9746, 59.9644) -> (13.7829, 61.6537)
  curve K17 (-5.8693, 54.9778) -> (-13.4249, 55.6114)
  curve K18 (-22.7131, 59.9644) -> (-25.5215, 61.6537)
  curve K19 (-32.7992, 60.4361) -> (-25.5215, 61.6537)
  curve K20 (-32.7992, 19.5622) -> (-25.5215, 18.3445)
  curve K21 (-22.7131, 20.0338) -> (-25.5215, 18.3445)
  curve K22 (-5.8693, 25.0204) -> (-13.4249, 24.3869)
  curve K23 (10.9746, 20.0338) -> (13.7829, 18.3445)
  curve K24 (13.7829, 18.3445) -> (21.0607, 19.5622)
  curve K25 (14.9178, 39.9991) -> (14.991, 38.4401)
  curve K26 (14.9178, 39.9991) -> (14.991, 41.5582)
  curve K27 (-21.2077, 58.9255) -> (-13.5094, 55.6283)
  curve K28 (-21.2077, 58.9255) -> (-21.4163, 59.0625)
  curve K29 (-21.2077, 21.0728) -> (-21.4163, 20.9358)
  curve K30 (-13.5094, 24.37) -> (-21.2077, 21.0728)
  curve K31 (-13.4249, 24.3869) -> (-13.5094, 24.37)
  curve K32 (1.6863, 24.3869) -> (1.7709, 24.37)
  curve K33 (9.4692, 21.0728) -> (1.7709, 24.37)
  curve K34 (9.4692, 21.0728) -> (9.6778, 20.9358)
  curve K35 (9.6778, 20.9358) -> (10.9746, 20.0338)
  curve K36 (9.6778, 59.0625) -> (10.9746, 59.9644)
  curve K37 (9.4692, 58.9255) -> (9.6778, 59.0625)
  curve K38 (1.7709, 55.6283) -> (9.4692, 58.9255)
  curve K39 (1.6863, 55.6114) -> (1.7709, 55.6283)
  curve K40 (-13.4249, 55.6114) -> (-13.5094, 55.6283)
  circle C1 centre (18.1307, 56.4991) radius 2.55
  circle C2 centre (18.1307, 23.4991) radius 2.55
  circle C3 centre (-29.8693, 56.4991) radius 2.55
  circle C4 centre (-29.8693, 23.4991) radius 2.55
  arc A1 centre (-39.8693, 43.8641) radius 6 clockwise from (-45.8693, 43.8641) to (-44.2889, 47.922)
  arc A2 centre (-39.8693, 36.1341) radius 6 clockwise from (-44.2889, 32.0762) to (-45.8693, 36.1341)
  arc A3 centre (-41.3693, 42.9991) radius 1.5 clockwise from (-41.3693, 41.4991) to (-41.3693, 44.4991)
  arc A4 centre (-23.7522, 42.9991) radius 1.5 clockwise from (-23.7522, 44.4991) to (-23.7522, 41.4991)
  arc A5 centre (-41.3693, 36.9991) radius 1.5 clockwise from (-41.3693, 35.4991) to (-41.3693, 38.4991)
  arc A6 centre (-23.7522, 36.9991) radius 1.5 clockwise from (-23.7522, 38.4991) to (-23.7522, 35.4991)
  arc A7 centre (17.3404, 55.6164) radius 6 clockwise from (21.7601, 59.6743) to (23.3399, 55.5369)
  arc A8 centre (17.3404, 24.3819) radius 6 clockwise from (23.3399, 24.4614) to (21.7601, 20.324)
  arc A9 centre (-26.3392, 30.9991) radius 1.5 clockwise from (-26.3392, 32.4991) to (-26.3392, 29.4991)
  arc A10 centre (-26.3392, 48.9991) radius 1.5 clockwise from (-26.3392, 50.4991) to (-26.3392, 47.4991)
  arc A11 centre (-34.3693, 30.9991) radius 1.5 clockwise from (-34.3693, 29.4991) to (-34.3693, 32.4991)
  arc A12 centre (-34.3693, 48.9991) radius 1.5 clockwise from (-34.3693, 47.4991) to (-34.3693, 50.4991)
  circle C5 centre (4.1307, 29.9991) radius 1.05
  circle C6 centre (-15.8693, 29.9991) radius 1.05
  circle C7 centre (4.1307, 49.9991) radius 1.05
  circle C8 centre (-15.8693, 49.9991) radius 1.05
  circle C9 centre (-5.8693, 39.9991) radius 2.55
  point P3 (-34.0692, 39.9991)
  point P2 (-32.8495, 19.3496)
  point P10 (-32.8495, 60.6486)
  point P11 (-34.0692, 39.9991)
  point P4 (-34.1, 36)
  point P14 (-34.1, 43.9982)
  point P5 (-34.0384, 43.9982)
  point P15 (-34.0384, 36)
  point P6 (-31.4834, 17.9871)
  point P12 (-31.4834, 62.0111)
  point P7 (-34.2156, 20.7121)
  point P13 (-34.2156, 59.2861)
  midpoint P3 K2
  midpoint P2 K3
  symmetric P2 L1 P10
  symmetric P3 L1 P11
  symmetric P4 L1 P14
  symmetric P5 L1 P15
  symmetric P6 L1 P12
  symmetric P7 L1 P13
extrude "Extrude76" cut sketch "top-chop" profile of K1 K4 L4 A1 L5 A2 L6 A3 L8 L9 A5 L10 L11 against normal blind 2
extrude "Extrude77" add sketch "top-chop" profile of K1 K4 L2 L8 L9 L10 L11 L12 L13 L14 L15 against normal blind 2
fillet "Fillet33" radius 1.5
component_insert "Komponente einfügen"
position "Position1"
